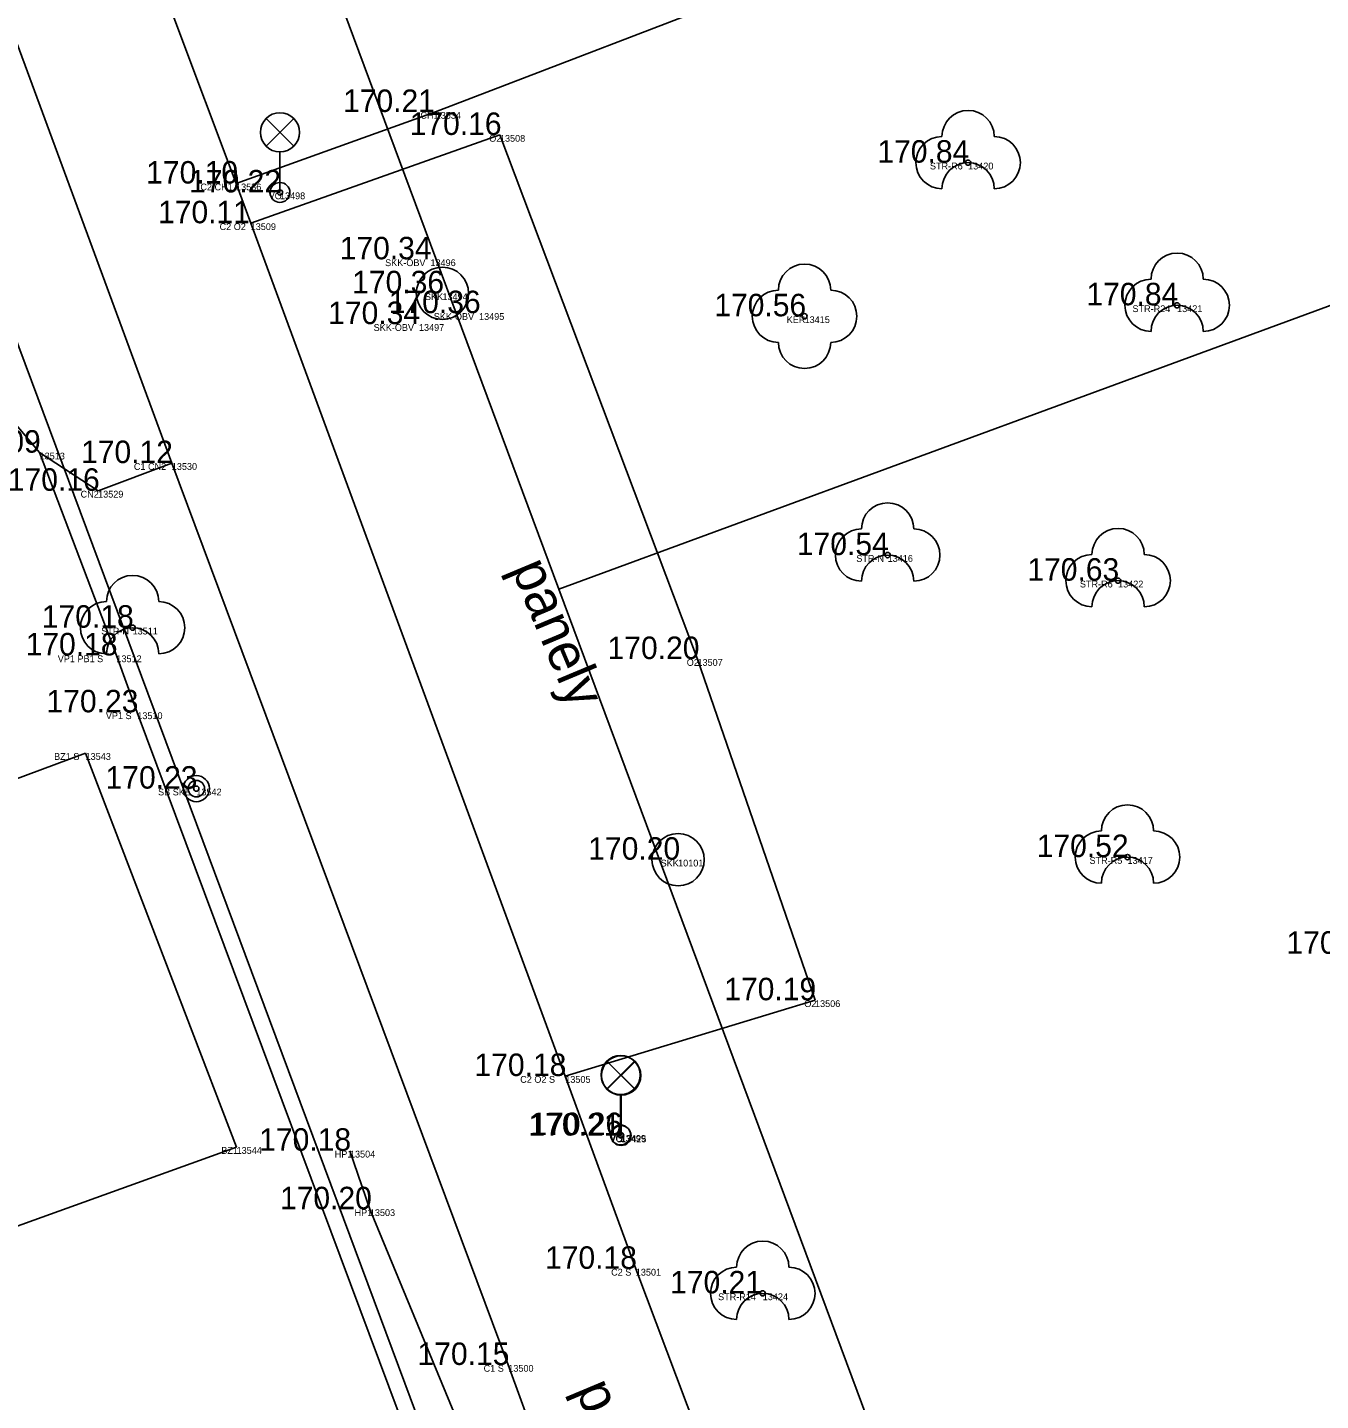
# Model space of a CAD drawing. Extents: x -566117 to -565580, y -1202428 to -1201938.
# Drawn here: x -565854.1 to -565829.36, y -1202258.29 to -1202232.01 of the extents above; entities that cross this region are included whole.
import ezdxf

# ---------------------------------------------------------------- set-up
doc = ezdxf.new("R2010")
doc.units = 0
for name, color, linetype in [('(Construction)', 7, 'Continuous'), ('Bod', 7, 'Continuous'), ('BUOVY_NEMĚŘ', 7, 'Continuous'), ('CIZÍ_NADZEM', 7, 'Continuous'), ('Implicitní', 7, 'Continuous'), ('Kanalizace', 7, 'Continuous'), ('Katastr', 7, 'Continuous'), ('Kod', 7, 'Continuous'), ('Oplocení', 7, 'Continuous'), ('POMOC_POPIS', 7, 'Continuous'), ('Vrstva 59', 7, 'Continuous'), ('Výška', 7, 'Continuous'), ('ZELEŇ', 7, 'Continuous'), ('Zpevněné plohy', 7, 'Continuous'), ('Číslo', 7, 'Continuous')]:
    doc.layers.add(name, color=color, linetype=linetype)

# ---------------------------------------------------------------- blocks, each defined once
blk = doc.blocks.new('A$C69D74C1E')
at = {"layer": 'Katastr'}
for p, q in [((221, -174.32), (204.38, -129.64)), ((210.32, -168.76), (218.9, -191.8)), ((233.16, -207.02), (221, -174.32))]:
    blk.add_line(p, q, dxfattribs=at)
blk.add_lwpolyline([(334.1, -183.79), (317.19, -138.94), (221, -174.32)], dxfattribs=at)
blk = doc.blocks.new('STROM')
at = {"layer": 'ZELEŇ'}
blk.add_circle((0, 0), 0.05, dxfattribs=at)
for centre, start, end in [((0, 0.5), 0, 180), ((-0.5, 0), 90, 270), ((0.5, 0), 270, 90), ((0, -0.5), 0, 180)]:
    blk.add_arc(centre, 0.5, start, end, dxfattribs=at)
blk = doc.blocks.new('3.13')
at = {"layer": 'ZELEŇ'}
blk.add_circle((0, 0), 0.1, dxfattribs=at)
for centre, start, end in [((0, 1), 0, 180), ((-1, 0), 90, 270), ((1, 0), 270, 90), ((0, -1), 180, 0)]:
    blk.add_arc(centre, 1, start, end, dxfattribs=at)
blk = doc.blocks.new('SAK')
at = {"layer": 'Kanalizace'}
blk.add_circle((0, 0), 0.5, dxfattribs=at)
blk = doc.blocks.new('LA')
at = {"layer": 'CIZÍ_NADZEM'}
for p, q in [((-0.265, 1.415), (0.265, 0.885)), ((-0.265, 0.885), (0.265, 1.415)), ((0, 0), (0, 0.775))]:
    blk.add_line(p, q, dxfattribs=at)
for centre, radius in [((0, 1.15), 0.375), ((0, 0), 0.19), ((0, 0), 0.05)]:
    blk.add_circle(centre, radius, dxfattribs=at)
blk = doc.blocks.new('SLB')
at = {"layer": 'CIZÍ_NADZEM'}
for radius in [0.25, 0.158, 0.05]:
    blk.add_circle((0, 0), radius, dxfattribs=at)
blk = doc.blocks.new('POINT_DISPLAY')
at = {"layer": 'Implicitní'}
blk.add_line((0, 0), (0, 0), dxfattribs=at)

msp = doc.modelspace()

# ---------------------------------------------------------------- linework, layer by layer
at = {"layer": '(Construction)'}
msp.add_line((-565852.99, -1202245.9), (-565850.1, -1202253.44), dxfattribs=at)
at = {"layer": 'BUOVY_NEMĚŘ'}
for p, q in [((-565852.99, -1202245.9), (-565857.52, -1202247.591)), ((-565850.1, -1202253.44), (-565863.16, -1202258.14))]:
    msp.add_line(p, q, dxfattribs=at)
at = {"layer": 'Oplocení'}
msp.add_line((-565852, -1202245.12), (-565852.4, -1202244.03), dxfattribs=at)
for points in [[(-565854.8, -1202239.05), (-565853.87, -1202240.15), (-565852.4, -1202244.03)], [(-565859.65, -1202267.3), (-565851.41, -1202264.57), (-565845.52, -1202262.48), (-565852, -1202245.12)]]:
    msp.add_lwpolyline(points, dxfattribs=at)
at = {"layer": 'ZELEŇ'}
for p, q in [((-565847.55, -1202254.63), (-565847.93, -1202253.51)), ((-565845.22, -1202260.25), (-565847.55, -1202254.63))]:
    msp.add_line(p, q, dxfattribs=at)
at = {"layer": 'Zpevněné plohy'}
for p, q in [((-565851.34, -1202240.35), (-565855.82, -1202228.21)), ((-565850.11, -1202235), (-565851.3, -1202231.82)), ((-565846.29, -1202233.63), (-565850.11, -1202235)), ((-565845.06, -1202234.07), (-565849.83, -1202235.76)), ((-565841.28, -1202244.1), (-565845.06, -1202234.07)), ((-565849.83, -1202235.76), (-565850.11, -1202235)), ((-565843.81, -1202252.08), (-565849.83, -1202235.76)), ((-565853.87, -1202240.15), (-565852.75, -1202240.88)), ((-565852.75, -1202240.88), (-565851.34, -1202240.35)), ((-565839.03, -1202250.63), (-565841.28, -1202244.1)), ((-565843.81, -1202252.08), (-565839.03, -1202250.63))]:
    msp.add_line(p, q, dxfattribs=at)
for points in [[(-565835.61, -1202229.57), (-565839.77, -1202231.12), (-565846.29, -1202233.63)], [(-565842.87, -1202263.19), (-565844.9, -1202257.61), (-565851.34, -1202240.35)], [(-565839.511, -1202263.6), (-565842.46, -1202255.77), (-565843.81, -1202252.08)]]:
    msp.add_lwpolyline(points, dxfattribs=at)

# ---------------------------------------------------------------- block references
at = {"layer": 'Bod'}
for p in [(-565846.29, -1202233.63), (-565845.06, -1202234.07), (-565836.1, -1202234.6), (-565850.11, -1202235), (-565849.27, -1202235.17), (-565849.83, -1202235.76), (-565846.39, -1202236.45), (-565846.16, -1202237.1), (-565832.1, -1202237.33), (-565845.46, -1202237.48), (-565839.23, -1202237.54), (-565846.61, -1202237.69), (-565853.87, -1202240.15), (-565851.34, -1202240.35), (-565852.75, -1202240.88), (-565837.64, -1202242.11), (-565833.23, -1202242.6), (-565852.09, -1202243.5), (-565852.4, -1202244.03), (-565841.28, -1202244.1), (-565852, -1202245.12), (-565852.99, -1202245.9), (-565850.87, -1202246.58), (-565841.65, -1202247.94), (-565833.05, -1202247.89), (-565839.03, -1202250.63), (-565843.81, -1202252.08), (-565842.75, -1202253.21), (-565842.74, -1202253.22), (-565850.1, -1202253.44), (-565847.93, -1202253.51), (-565847.55, -1202254.63), (-565842.46, -1202255.77), (-565840.03, -1202256.24), (-565844.9, -1202257.61)]:
    msp.add_blockref('POINT_DISPLAY', p, dxfattribs=at)
at = {"layer": 'CIZÍ_NADZEM'}
for name, p in [('LA', (-565849.27, -1202235.17)), ('SLB', (-565850.87, -1202246.58)), ('LA', (-565842.75, -1202253.21)), ('LA', (-565842.74, -1202253.22))]:
    msp.add_blockref(name, p, dxfattribs=at)
at = {"layer": 'Implicitní'}
msp.add_blockref('A$C69D74C1E', (-566064.93, -1202068.44), dxfattribs=at)
at = {"layer": 'Kanalizace'}
for p in [(-565846.16, -1202237.1), (-565841.65, -1202247.94)]:
    msp.add_blockref('SAK', p, dxfattribs=at)
at = {"layer": 'Vrstva 59', "xscale": 0.5, "yscale": 0.5}
msp.add_blockref('3.13', (-565839.23, -1202237.54), dxfattribs=at)
at = {"layer": 'ZELEŇ'}
for p in [(-565836.1, -1202234.6), (-565832.1, -1202237.33), (-565837.64, -1202242.11), (-565833.23, -1202242.6), (-565852.09, -1202243.5), (-565833.05, -1202247.89), (-565840.03, -1202256.24)]:
    msp.add_blockref('STROM', p, dxfattribs=at)

# ---------------------------------------------------------------- texts
at = {"layer": 'Kod'}
for s, p in [('CH1', (-565846.582, -1202233.76)), ('O2', (-565845.265, -1202234.2)), ('STR-R6', (-565836.831, -1202234.73)), ('C2 CH1', (-565850.792, -1202235.13)), ('VO', (-565849.486, -1202235.3)), ('C2 O2', (-565850.425, -1202235.89)), ('SKK-OBV', (-565847.257, -1202236.58)), ('SKK', (-565846.495, -1202237.23)), ('STR-R24', (-565832.955, -1202237.46)), ('SKK-OBV', (-565846.327, -1202237.61)), ('KER', (-565839.571, -1202237.67)), ('SKK-OBV', (-565847.477, -1202237.82)), ('C1 CN2', (-565852.065, -1202240.48)), ('CN2', (-565853.085, -1202241.01)), ('STR-N', (-565838.241, -1202242.24)), ('STR-R6', (-565833.961, -1202242.73)), ('STR-N', (-565852.691, -1202243.63)), ('VP1 PB1 S', (-565853.522, -1202244.16)), ('O2', (-565841.485, -1202244.23)), ('VP1 S', (-565852.602, -1202245.25)), ('BZ1 S', (-565853.592, -1202246.03)), ('SB SKE', (-565851.602, -1202246.71)), ('SKK', (-565841.985, -1202248.07)), ('STR-R5', (-565833.777, -1202248.02)), ('O2', (-565839.235, -1202250.76)), ('C2 O2 S', (-565844.672, -1202252.21)), ('VO', (-565842.966, -1202253.34)), ('VO', (-565842.956, -1202253.35)), ('BZ1', (-565850.392, -1202253.57)), ('HP1', (-565848.222, -1202253.64)), ('HP1', (-565847.842, -1202254.76)), ('C2 S', (-565842.932, -1202255.9)), ('STR-R14', (-565840.885, -1202256.37)), ('C1 S', (-565845.372, -1202257.74))]:
    msp.add_text(s, height=0.13, dxfattribs=at).set_placement(p)
at = {"layer": 'POMOC_POPIS'}
for p in [(-565844.852, -1202242.364), (-565843.624, -1202258.076)]:
    msp.add_text('panely', height=0.75, rotation=292.7197, dxfattribs=at).set_placement(p)
at = {"layer": 'Výška'}
for s, p in [('170.21 ', (-565848.063, -1202233.63)), ('170.16 ', (-565846.788, -1202234.07)), ('170.84 ', (-565837.837, -1202234.6)), ('170.10 ', (-565851.83, -1202235)), ('170.22 ', (-565851.007, -1202235.17)), ('170.11 ', (-565851.603, -1202235.76)), ('170.34 ', (-565848.127, -1202236.45)), ('170.36 ', (-565847.888, -1202237.1)), ('170.36 ', (-565847.188, -1202237.48)), ('170.84 ', (-565833.837, -1202237.33)), ('170.34 ', (-565848.347, -1202237.69)), ('170.56 ', (-565840.958, -1202237.54)), ('170.09 ', (-565855.607, -1202240.15)), ('170.12 ', (-565853.077, -1202240.35)), ('170.16 ', (-565854.478, -1202240.88)), ('170.54 ', (-565839.377, -1202242.11)), ('170.63 ', (-565834.967, -1202242.6)), ('170.18 ', (-565853.827, -1202243.5)), ('170.18 ', (-565854.137, -1202244.03)), ('170.20 ', (-565843, -1202244.1)), ('170.23 ', (-565853.737, -1202245.12)), ('170.23 ', (-565852.607, -1202246.58)), ('170.20 ', (-565843.37, -1202247.94)), ('170.52 ', (-565834.787, -1202247.89)), ('170.65 ', (-565830.007, -1202249.74)), ('170.19 ', (-565840.767, -1202250.63)), ('170.18 ', (-565845.547, -1202252.08)), ('170.21 ', (-565844.513, -1202253.22)), ('170.26 ', (-565844.478, -1202253.21)), ('170.18 ', (-565849.667, -1202253.51)), ('170.20 ', (-565849.27, -1202254.63)), ('170.18 ', (-565844.197, -1202255.77)), ('170.21 ', (-565841.803, -1202256.24)), ('170.15 ', (-565846.637, -1202257.61))]:
    msp.add_text(s, height=0.43, dxfattribs=at).set_placement(p)
at = {"layer": 'Číslo'}
for s, p in [('13534', (-565846.29, -1202233.76)), ('13508', (-565845.06, -1202234.2)), ('13420', (-565836.1, -1202234.73)), ('13536', (-565850.11, -1202235.13)), ('13498', (-565849.27, -1202235.3)), ('13509', (-565849.83, -1202235.89)), ('13496', (-565846.39, -1202236.58)), ('13494', (-565846.16, -1202237.23)), ('13421', (-565832.1, -1202237.46)), ('13495', (-565845.46, -1202237.61)), ('13415', (-565839.23, -1202237.67)), ('13497', (-565846.61, -1202237.82)), ('13513', (-565853.87, -1202240.28)), ('13530', (-565851.34, -1202240.48)), ('13529', (-565852.75, -1202241.01)), ('13416', (-565837.64, -1202242.24)), ('13422', (-565833.23, -1202242.73)), ('13511', (-565852.09, -1202243.63)), ('13512', (-565852.4, -1202244.16)), ('13507', (-565841.28, -1202244.23)), ('13510', (-565852, -1202245.25)), ('13543', (-565852.99, -1202246.03)), ('13542', (-565850.87, -1202246.71)), ('10101', (-565841.65, -1202248.07)), ('13417', (-565833.05, -1202248.02)), ('13506', (-565839.03, -1202250.76)), ('13505', (-565843.81, -1202252.21)), ('13499', (-565842.75, -1202253.34)), ('13425', (-565842.74, -1202253.35)), ('13544', (-565850.1, -1202253.57)), ('13504', (-565847.93, -1202253.64)), ('13503', (-565847.55, -1202254.76)), ('13501', (-565842.46, -1202255.9)), ('13424', (-565840.03, -1202256.37)), ('13500', (-565844.9, -1202257.74))]:
    msp.add_text(s, height=0.13, dxfattribs=at).set_placement(p)

doc.saveas('drawing.dxf')
